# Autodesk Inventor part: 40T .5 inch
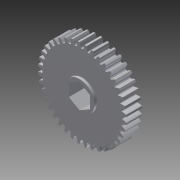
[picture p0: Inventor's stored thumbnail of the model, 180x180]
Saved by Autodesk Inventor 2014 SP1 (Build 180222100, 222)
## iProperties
Created: 2014-11
Part Number: 40T .5 inch
Material: Aluminum 6061
Document SubType Name: Modeling
Designer: Michael
Density: 2.71 g/cm^3
Appearance: Aluminum - Flat
Author: svradm
Title: 217-2708.20121204.STEP
Organization: Microsoft
Description: STEP AP203
Creation Date: 2012-12-05
Sending System: SolidWorks 2012
Preprocessor: SwSTEP 2.0
Author: Michael
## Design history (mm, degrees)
node "40T .5 inch1"
node "Combine1"
node "Base1"
